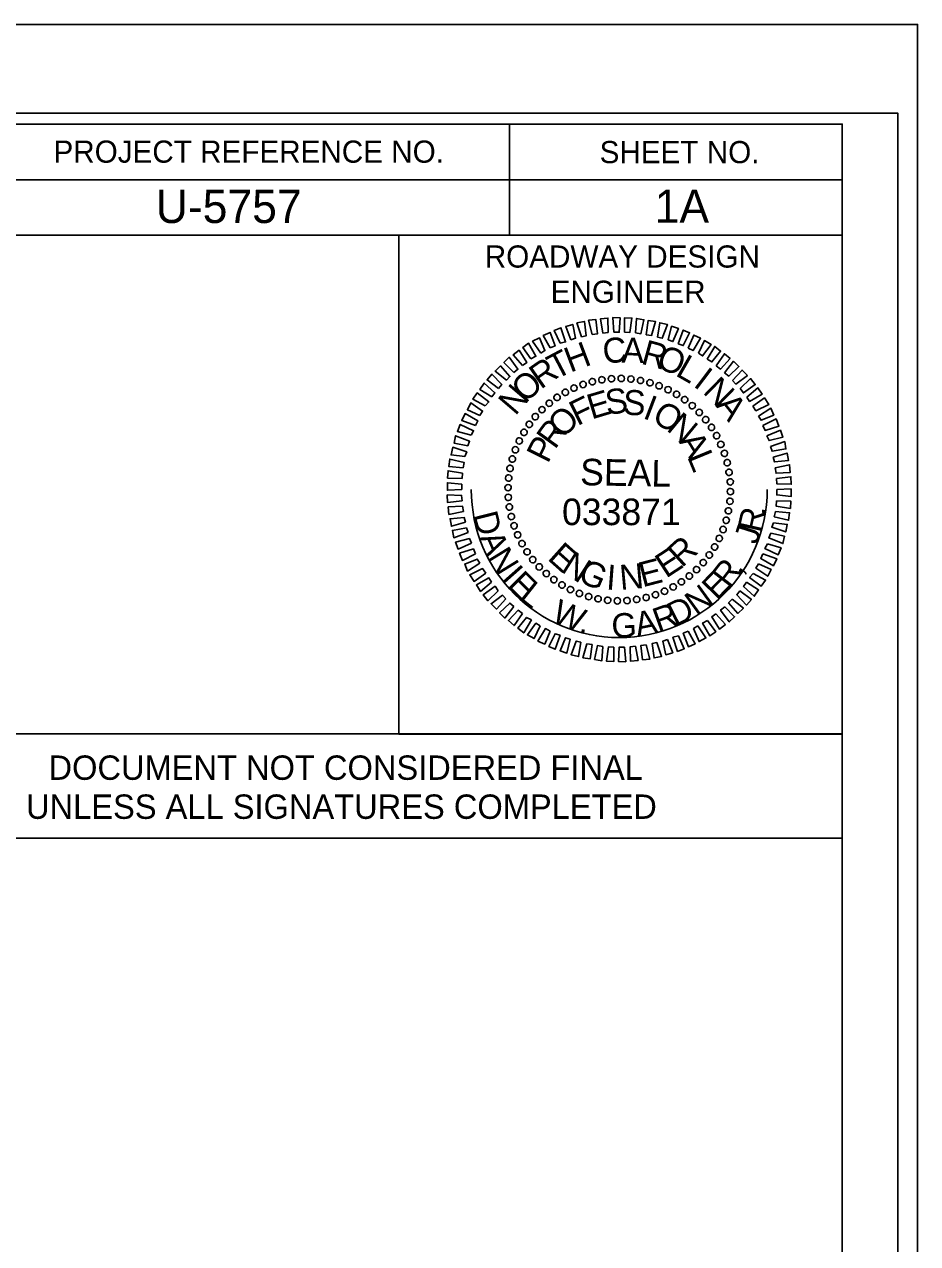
# Model space of a CAD drawing. Extents: x 1537922 to 1539606, y 409903 to 410998.
# Drawn here: x 1539404.5 to 1539605.9, y 410723.4 to 410998.4 of the extents above; entities that cross this region are included whole.
import ezdxf

# ---------------------------------------------------------------- set-up
doc = ezdxf.new("R2010")
doc.units = 0
for name, color, linetype in [('Scratch_Level_0', 7, 'Continuous'), ('Sheet Cutting Line CELL', 7, 'Continuous'), ('Sheet Data Field CELL', 7, 'Continuous'), ('Sheet Plan CELL', 7, 'Continuous'), ('Sheet Plot Border Inside CELL', 7, 'Continuous'), ('Sheet Plot Border Outside CELL', 7, 'Continuous'), ('Sheet Professional Seal CELL', 7, 'Continuous'), ('Sheet Profile Grid Minor CELL', 7, 'Continuous'), ('Sheet Sticker Exception Certification CELL', 7, 'Continuous')]:
    doc.layers.add(name, color=color, linetype=linetype)

msp = doc.modelspace()

# ---------------------------------------------------------------- linework, layer by layer
at = {"layer": 'Scratch_Level_0'}
msp.add_arc((1539538.59, 410893.42), 33.36, 180, 360, dxfattribs=at)
at = {"layer": 'Sheet Cutting Line CELL'}
msp.add_line((1539605.87, 410998.35), (1537922.37, 410998.35), dxfattribs=at)
at = {"layer": 'Sheet Plan CELL'}
for p, q in [((1539513.87, 410975.8), (1539513.87, 410950.8)), ((1539388.82, 410963.3), (1539588.87, 410963.3)), ((1539388.82, 410950.8), (1539588.87, 410950.8)), ((1539388.82, 410950.8), (1539588.87, 410950.8)), ((1539488.87, 410950.8), (1539488.87, 410838.35))]:
    msp.add_line(p, q, dxfattribs=at)
for points in [[(1539588.87, 410975.85), (1538088.87, 410975.85), (1538088.87, 409925.85), (1539588.87, 409925.85)], [(1539388.82, 410975.85), (1539588.87, 410975.85), (1539588.87, 410950.8), (1539388.82, 410950.8)], [(1539488.87, 410950.8), (1539588.87, 410950.8), (1539588.87, 410838.3), (1539488.87, 410838.3)]]:
    msp.add_lwpolyline(points, close=True, dxfattribs=at)
at = {"layer": 'Sheet Plot Border Inside CELL'}
msp.add_lwpolyline([(1537935.37, 409923.35), (1539601.37, 409923.35), (1539601.37, 410978.35), (1537935.37, 410978.35)], close=True, dxfattribs=at)
at = {"layer": 'Sheet Plot Border Outside CELL'}
msp.add_lwpolyline([(1537922.37, 409903.35), (1539605.87, 409903.35), (1539605.87, 410998.35), (1537922.37, 410998.35)], close=True, dxfattribs=at)
at = {"layer": 'Sheet Professional Seal CELL'}
for p, q in [((1539534.69, 410918.17), (1539534.69, 410918.17)), ((1539536.84, 410918.47), (1539536.84, 410918.47)), ((1539539.04, 410918.52), (1539539.04, 410918.52)), ((1539541.24, 410918.37), (1539541.24, 410918.37)), ((1539543.39, 410918.02), (1539543.39, 410918.02)), ((1539526.44, 410915.37), (1539526.44, 410915.37)), ((1539528.39, 410916.37), (1539528.39, 410916.37)), ((1539530.39, 410917.17), (1539530.39, 410917.17)), ((1539532.49, 410917.77), (1539532.49, 410917.77)), ((1539545.49, 410917.57), (1539545.49, 410917.57)), ((1539547.59, 410916.87), (1539547.59, 410916.87)), ((1539549.59, 410915.97), (1539549.59, 410915.97)), ((1539522.79, 410912.97), (1539522.79, 410912.97)), ((1539524.54, 410914.22), (1539524.54, 410914.22)), ((1539551.54, 410914.97), (1539551.54, 410914.97)), ((1539553.34, 410913.72), (1539553.34, 410913.72)), ((1539519.64, 410909.92), (1539519.64, 410909.92)), ((1539521.14, 410911.47), (1539521.14, 410911.47)), ((1539555.09, 410912.37), (1539555.09, 410912.37)), ((1539556.64, 410910.87), (1539556.64, 410910.87)), ((1539518.29, 410908.17), (1539518.29, 410908.17)), ((1539558.14, 410909.22), (1539558.14, 410909.22)), ((1539559.39, 410907.47), (1539559.39, 410907.47)), ((1539516.04, 410904.42), (1539516.04, 410904.42)), ((1539517.04, 410906.37), (1539517.04, 410906.37)), ((1539560.54, 410905.57), (1539560.54, 410905.57)), ((1539515.14, 410902.42), (1539515.14, 410902.42)), ((1539561.54, 410903.62), (1539561.54, 410903.62)), ((1539562.34, 410901.62), (1539562.34, 410901.62)), ((1539514.44, 410900.32), (1539514.44, 410900.32)), ((1539562.94, 410899.52), (1539562.94, 410899.52)), ((1539513.64, 410896.07), (1539513.64, 410896.07)), ((1539513.99, 410898.22), (1539513.99, 410898.22)), ((1539563.34, 410897.32), (1539563.34, 410897.32)), ((1539513.49, 410893.87), (1539513.49, 410893.87)), ((1539538.59, 410893.42), (1539538.59, 410893.42)), ((1539563.64, 410895.17), (1539563.64, 410895.17)), ((1539513.54, 410891.67), (1539513.54, 410891.67)), ((1539563.54, 410890.77), (1539563.54, 410890.77)), ((1539563.69, 410892.97), (1539563.69, 410892.97)), ((1539513.84, 410889.52), (1539513.84, 410889.52)), ((1539563.19, 410888.62), (1539563.19, 410888.62)), ((1539514.24, 410887.32), (1539514.24, 410887.32)), ((1539514.84, 410885.22), (1539514.84, 410885.22)), ((1539562.74, 410886.52), (1539562.74, 410886.52)), ((1539515.64, 410883.22), (1539515.64, 410883.22)), ((1539561.14, 410882.42), (1539561.14, 410882.42)), ((1539562.04, 410884.42), (1539562.04, 410884.42)), ((1539516.64, 410881.27), (1539516.64, 410881.27)), ((1539560.14, 410880.47), (1539560.14, 410880.47)), ((1539517.79, 410879.37), (1539517.79, 410879.37)), ((1539519.04, 410877.62), (1539519.04, 410877.62)), ((1539557.54, 410876.92), (1539557.54, 410876.92)), ((1539558.89, 410878.67), (1539558.89, 410878.67)), ((1539520.54, 410875.97), (1539520.54, 410875.97)), ((1539522.09, 410874.47), (1539522.09, 410874.47)), ((1539556.04, 410875.37), (1539556.04, 410875.37)), ((1539523.84, 410873.12), (1539523.84, 410873.12)), ((1539525.64, 410871.87), (1539525.64, 410871.87)), ((1539550.74, 410871.47), (1539550.74, 410871.47)), ((1539552.64, 410872.62), (1539552.64, 410872.62)), ((1539554.39, 410873.87), (1539554.39, 410873.87)), ((1539527.59, 410870.87), (1539527.59, 410870.87)), ((1539529.59, 410869.97), (1539529.59, 410869.97)), ((1539531.69, 410869.27), (1539531.69, 410869.27)), ((1539533.79, 410868.82), (1539533.79, 410868.82)), ((1539542.49, 410868.67), (1539542.49, 410868.67)), ((1539544.69, 410869.07), (1539544.69, 410869.07)), ((1539546.79, 410869.67), (1539546.79, 410869.67)), ((1539548.79, 410870.47), (1539548.79, 410870.47)), ((1539535.94, 410868.47), (1539535.94, 410868.47)), ((1539538.14, 410868.32), (1539538.14, 410868.32)), ((1539540.34, 410868.37), (1539540.34, 410868.37))]:
    msp.add_line(p, q, dxfattribs=at)
for points in [[(1539532.49, 410928.42), (1539531.69, 410931.62), (1539533.34, 410931.77), (1539533.69, 410928.57)], [(1539534.89, 410928.72), (1539534.34, 410931.92), (1539536.04, 410932.12), (1539536.09, 410928.87)], [(1539537.39, 410928.97), (1539537.14, 410932.22), (1539538.79, 410932.17), (1539538.59, 410928.92)], [(1539539.79, 410928.92), (1539539.79, 410932.17), (1539541.44, 410932.12), (1539540.99, 410928.87)], [(1539542.29, 410928.77), (1539542.49, 410932.02), (1539544.14, 410931.72), (1539543.49, 410928.57)], [(1539525.24, 410926.42), (1539523.94, 410929.32), (1539525.44, 410929.92), (1539526.49, 410926.72)], [(1539527.69, 410927.22), (1539526.54, 410930.22), (1539528.09, 410930.67), (1539528.74, 410927.57)], [(1539530.09, 410927.87), (1539529.04, 410931.02), (1539530.74, 410931.37), (1539531.14, 410928.12)], [(1539544.69, 410928.37), (1539545.14, 410931.57), (1539546.79, 410931.32), (1539545.89, 410928.22)], [(1539547.24, 410927.82), (1539547.74, 410931.07), (1539549.44, 410930.67), (1539548.29, 410927.57)], [(1539549.64, 410927.17), (1539550.39, 410930.27), (1539551.94, 410929.77), (1539550.69, 410926.82)], [(1539551.89, 410926.27), (1539553.04, 410929.42), (1539554.44, 410928.82), (1539553.04, 410925.92)], [(1539518.69, 410922.92), (1539516.84, 410925.47), (1539518.14, 410926.42), (1539519.79, 410923.52)], [(1539520.89, 410924.17), (1539519.04, 410926.87), (1539520.59, 410927.67), (1539521.84, 410924.77)], [(1539523.04, 410925.37), (1539521.44, 410928.17), (1539522.99, 410928.87), (1539524.14, 410925.82)], [(1539554.14, 410925.32), (1539555.39, 410928.27), (1539556.94, 410927.57), (1539555.24, 410924.77)], [(1539556.44, 410924.17), (1539557.79, 410927.02), (1539559.29, 410926.17), (1539557.39, 410923.57)], [(1539516.79, 410921.42), (1539514.64, 410923.82), (1539515.99, 410924.87), (1539517.74, 410922.07)], [(1539558.39, 410922.82), (1539560.14, 410925.72), (1539561.44, 410924.67), (1539559.49, 410922.22)], [(1539560.44, 410921.32), (1539562.29, 410924.07), (1539563.59, 410922.97), (1539561.39, 410920.62)], [(1539513.14, 410918.12), (1539510.59, 410920.17), (1539511.84, 410921.32), (1539513.94, 410918.92)], [(1539514.79, 410919.87), (1539512.59, 410922.07), (1539513.79, 410923.27), (1539515.74, 410920.57)], [(1539562.34, 410919.77), (1539564.39, 410922.37), (1539565.59, 410921.17), (1539563.29, 410919.02)], [(1539511.39, 410916.22), (1539508.79, 410918.17), (1539509.89, 410919.47), (1539512.09, 410917.12)], [(1539564.14, 410918.02), (1539566.29, 410920.37), (1539567.49, 410919.17), (1539564.89, 410917.22)], [(1539565.89, 410916.22), (1539568.19, 410918.47), (1539569.24, 410917.12), (1539566.59, 410915.22)], [(1539509.89, 410914.32), (1539507.19, 410916.02), (1539508.14, 410917.47), (1539510.54, 410915.27)], [(1539567.39, 410914.27), (1539569.84, 410916.37), (1539570.79, 410914.92), (1539567.99, 410913.32)], [(1539507.19, 410910.17), (1539504.34, 410911.42), (1539505.09, 410912.97), (1539507.79, 410911.12)], [(1539508.39, 410912.32), (1539505.59, 410913.82), (1539506.59, 410915.22), (1539509.19, 410913.22)], [(1539568.69, 410912.22), (1539571.34, 410914.12), (1539572.29, 410912.62), (1539569.39, 410911.22)], [(1539506.19, 410907.87), (1539503.09, 410909.02), (1539503.84, 410910.57), (1539506.69, 410908.97)], [(1539569.99, 410910.02), (1539572.79, 410911.77), (1539573.44, 410910.22), (1539570.59, 410909.07)], [(1539505.19, 410905.67), (1539502.09, 410906.57), (1539502.74, 410908.12), (1539505.74, 410906.72)], [(1539570.99, 410907.87), (1539573.94, 410909.37), (1539574.59, 410907.77), (1539571.49, 410906.77)], [(1539504.44, 410903.27), (1539501.34, 410903.92), (1539501.69, 410905.57), (1539504.84, 410904.32)], [(1539571.89, 410905.52), (1539574.94, 410906.82), (1539575.49, 410905.27), (1539572.39, 410904.47)], [(1539572.69, 410903.12), (1539575.89, 410904.27), (1539576.19, 410902.62), (1539573.04, 410902.07)], [(1539503.79, 410900.87), (1539500.69, 410901.27), (1539501.04, 410902.97), (1539504.19, 410901.92)], [(1539573.29, 410900.72), (1539576.44, 410901.67), (1539576.74, 410899.97), (1539573.59, 410899.67)], [(1539503.39, 410898.32), (1539500.19, 410898.62), (1539500.39, 410900.32), (1539503.64, 410899.52)], [(1539573.74, 410898.32), (1539576.99, 410899.02), (1539577.14, 410897.32), (1539573.94, 410897.12)], [(1539503.14, 410895.92), (1539499.89, 410896.02), (1539499.99, 410897.67), (1539503.24, 410897.12)], [(1539574.04, 410895.92), (1539577.29, 410896.32), (1539577.39, 410894.62), (1539574.14, 410894.72)], [(1539503.09, 410893.42), (1539499.84, 410893.27), (1539499.84, 410894.97), (1539503.09, 410894.62)], [(1539574.09, 410893.42), (1539577.34, 410893.57), (1539577.34, 410891.87), (1539574.09, 410892.22)], [(1539503.14, 410890.92), (1539499.89, 410890.52), (1539499.79, 410892.22), (1539503.04, 410892.12)], [(1539574.04, 410890.92), (1539577.29, 410890.82), (1539577.19, 410889.17), (1539573.94, 410889.72)], [(1539503.44, 410888.52), (1539500.19, 410887.82), (1539500.04, 410889.52), (1539503.24, 410889.72)], [(1539573.79, 410888.52), (1539576.99, 410888.22), (1539576.79, 410886.52), (1539573.54, 410887.32)], [(1539503.89, 410886.12), (1539500.74, 410885.17), (1539500.44, 410886.87), (1539503.59, 410887.17)], [(1539573.39, 410885.97), (1539576.49, 410885.57), (1539576.14, 410883.87), (1539572.99, 410884.92)], [(1539504.49, 410883.72), (1539501.29, 410882.57), (1539500.99, 410884.22), (1539504.14, 410884.77)], [(1539505.29, 410881.32), (1539502.24, 410880.02), (1539501.69, 410881.57), (1539504.79, 410882.37)], [(1539572.74, 410883.57), (1539575.84, 410882.92), (1539575.49, 410881.27), (1539572.34, 410882.52)], [(1539506.19, 410878.97), (1539503.24, 410877.47), (1539502.59, 410879.07), (1539505.69, 410880.07)], [(1539571.99, 410881.17), (1539575.09, 410880.27), (1539574.44, 410878.72), (1539571.44, 410880.12)], [(1539507.19, 410876.82), (1539504.39, 410875.07), (1539503.74, 410876.62), (1539506.59, 410877.77)], [(1539570.99, 410878.97), (1539574.09, 410877.82), (1539573.34, 410876.27), (1539570.49, 410877.87)], [(1539508.49, 410874.62), (1539505.84, 410872.72), (1539504.89, 410874.22), (1539507.79, 410875.62)], [(1539568.79, 410874.52), (1539571.59, 410873.02), (1539570.59, 410871.62), (1539567.99, 410873.62)], [(1539569.99, 410876.67), (1539572.84, 410875.42), (1539572.09, 410873.87), (1539569.39, 410875.72)], [(1539509.79, 410872.57), (1539507.34, 410870.47), (1539506.39, 410871.92), (1539509.19, 410873.52)], [(1539511.29, 410870.62), (1539508.99, 410868.37), (1539507.94, 410869.72), (1539510.59, 410871.62)], [(1539567.29, 410872.52), (1539569.99, 410870.82), (1539569.04, 410869.37), (1539566.64, 410871.57)], [(1539513.04, 410868.82), (1539510.89, 410866.47), (1539509.69, 410867.67), (1539512.29, 410869.62)], [(1539564.04, 410868.72), (1539566.59, 410866.67), (1539565.34, 410865.52), (1539563.24, 410867.92)], [(1539565.79, 410870.62), (1539568.39, 410868.67), (1539567.29, 410867.37), (1539565.09, 410869.72)], [(1539514.84, 410867.07), (1539512.79, 410864.47), (1539511.59, 410865.67), (1539513.89, 410867.82)], [(1539516.74, 410865.52), (1539514.89, 410862.77), (1539513.59, 410863.87), (1539515.79, 410866.22)], [(1539562.39, 410866.97), (1539564.59, 410864.77), (1539563.39, 410863.57), (1539561.44, 410866.27)], [(1539518.79, 410864.02), (1539517.04, 410861.12), (1539515.74, 410862.17), (1539517.69, 410864.62)], [(1539520.74, 410862.67), (1539519.39, 410859.82), (1539517.89, 410860.67), (1539519.79, 410863.27)], [(1539558.49, 410863.92), (1539560.34, 410861.37), (1539559.04, 410860.42), (1539557.39, 410863.32)], [(1539560.39, 410865.42), (1539562.54, 410863.02), (1539561.19, 410861.97), (1539559.44, 410864.77)], [(1539523.04, 410861.52), (1539521.79, 410858.57), (1539520.24, 410859.27), (1539521.94, 410862.07)], [(1539525.29, 410860.57), (1539524.14, 410857.42), (1539522.74, 410858.02), (1539524.14, 410860.92)], [(1539551.94, 410860.42), (1539553.24, 410857.52), (1539551.74, 410856.92), (1539550.69, 410860.12)], [(1539554.14, 410861.47), (1539555.74, 410858.67), (1539554.19, 410857.97), (1539553.04, 410861.02)], [(1539556.29, 410862.67), (1539558.14, 410859.97), (1539556.59, 410859.17), (1539555.34, 410862.07)], [(1539527.54, 410859.67), (1539526.79, 410856.57), (1539525.24, 410857.07), (1539526.49, 410860.02)], [(1539529.94, 410859.02), (1539529.44, 410855.77), (1539527.74, 410856.17), (1539528.89, 410859.27)], [(1539532.49, 410858.47), (1539532.04, 410855.27), (1539530.39, 410855.52), (1539531.29, 410858.62)], [(1539534.89, 410858.07), (1539534.69, 410854.82), (1539533.04, 410855.12), (1539533.69, 410858.27)], [(1539537.39, 410857.92), (1539537.39, 410854.67), (1539535.74, 410854.72), (1539536.19, 410857.97)], [(1539539.79, 410857.87), (1539540.04, 410854.62), (1539538.39, 410854.67), (1539538.59, 410857.92)], [(1539542.29, 410858.12), (1539542.84, 410854.92), (1539541.14, 410854.72), (1539541.09, 410857.97)], [(1539544.69, 410858.42), (1539545.49, 410855.22), (1539543.84, 410855.07), (1539543.49, 410858.27)], [(1539547.09, 410858.97), (1539548.14, 410855.82), (1539546.44, 410855.47), (1539546.04, 410858.72)], [(1539549.49, 410859.62), (1539550.64, 410856.62), (1539549.09, 410856.17), (1539548.44, 410859.27)]]:
    msp.add_lwpolyline(points, close=True, dxfattribs=at)
for centre, major_axis in [((1539532.53, 410917.76), (-0.174, 0.699)), ((1539534.67, 410918.19), (-0.113, 0.711)), ((1539536.84, 410918.44), (-0.05, 0.718)), ((1539539.03, 410918.5), (0.013, 0.72)), ((1539541.21, 410918.36), (0.075, 0.716)), ((1539543.38, 410918.04), (0.137, 0.707)), ((1539545.51, 410917.53), (0.198, 0.692)), ((1539526.43, 410915.36), (-0.349, 0.63)), ((1539528.39, 410916.33), (-0.293, 0.658)), ((1539530.43, 410917.13), (-0.234, 0.681)), ((1539547.58, 410916.84), (0.258, 0.672)), ((1539549.59, 410915.96), (0.316, 0.647)), ((1539551.51, 410914.92), (0.371, 0.617)), ((1539522.81, 410912.91), (-0.453, 0.56)), ((1539524.57, 410914.21), (-0.403, 0.597)), ((1539553.33, 410913.71), (0.423, 0.582)), ((1539555.05, 410912.35), (0.472, 0.543)), ((1539519.66, 410909.88), (-0.543, 0.472)), ((1539521.17, 410911.46), (-0.5, 0.518)), ((1539556.63, 410910.84), (0.518, 0.5)), ((1539558.08, 410909.2), (0.56, 0.453)), ((1539517.1, 410906.34), (-0.617, 0.371)), ((1539518.3, 410908.16), (-0.582, 0.423)), ((1539559.39, 410907.45), (0.597, 0.403)), ((1539516.05, 410904.42), (-0.647, 0.316)), ((1539560.53, 410905.58), (0.63, 0.349)), ((1539561.5, 410903.62), (0.658, 0.293)), ((1539515.18, 410902.41), (-0.672, 0.258)), ((1539562.31, 410901.59), (0.681, 0.234)), ((1539513.97, 410898.21), (-0.707, 0.137)), ((1539514.48, 410900.33), (-0.692, 0.198)), ((1539562.93, 410899.49), (0.699, 0.174)), ((1539513.65, 410896.04), (-0.716, 0.075)), ((1539563.36, 410897.34), (0.711, 0.113)), ((1539513.52, 410893.86), (-0.72, 0.013)), ((1539563.61, 410895.17), (0.718, 0.05)), ((1539563.67, 410892.98), (0.72, -0.013)), ((1539513.57, 410891.67), (-0.718, -0.05)), ((1539563.54, 410890.8), (0.716, -0.075)), ((1539513.82, 410889.5), (-0.711, -0.113)), ((1539514.26, 410887.35), (-0.699, -0.174)), ((1539563.21, 410888.64), (0.707, -0.137)), ((1539514.88, 410885.26), (-0.681, -0.234)), ((1539562.01, 410884.43), (0.672, -0.258)), ((1539562.7, 410886.51), (0.692, -0.198)), ((1539515.68, 410883.22), (-0.658, -0.293)), ((1539561.13, 410882.43), (0.647, -0.316)), ((1539516.66, 410881.26), (-0.63, -0.349)), ((1539517.8, 410879.4), (-0.597, -0.403)), ((1539558.88, 410878.68), (0.582, -0.423)), ((1539560.09, 410880.5), (0.617, -0.371)), ((1539519.1, 410877.64), (-0.56, -0.453)), ((1539520.55, 410876), (-0.518, -0.5)), ((1539557.52, 410876.97), (0.543, -0.472)), ((1539522.14, 410874.49), (-0.472, -0.543)), ((1539554.38, 410873.93), (0.453, -0.56)), ((1539556.02, 410875.38), (0.5, -0.518)), ((1539523.85, 410873.13), (-0.423, -0.582)), ((1539525.68, 410871.92), (-0.371, -0.617)), ((1539527.6, 410870.88), (-0.316, -0.647)), ((1539548.79, 410870.51), (0.293, -0.658)), ((1539550.75, 410871.49), (0.349, -0.63)), ((1539552.62, 410872.63), (0.403, -0.597)), ((1539529.61, 410870.01), (-0.258, -0.672)), ((1539531.68, 410869.31), (-0.198, -0.692)), ((1539533.81, 410868.8), (-0.137, -0.707)), ((1539535.97, 410868.48), (-0.075, -0.716)), ((1539538.16, 410868.34), (-0.013, -0.72)), ((1539540.34, 410868.4), (0.05, -0.718)), ((1539542.52, 410868.65), (0.113, -0.711)), ((1539544.66, 410869.09), (0.174, -0.699)), ((1539546.76, 410869.71), (0.234, -0.681))]:
    msp.add_ellipse(centre, major_axis=major_axis, ratio=0.999708, dxfattribs=at)
at = {"layer": 'Sheet Sticker Exception Certification CELL'}
for p, q in [((1539388.83, 410838.31), (1539588.87, 410838.31)), ((1539588.87, 410838.3), (1539588.87, 410814.8)), ((1539588.87, 410814.81), (1539388.83, 410814.81))]:
    msp.add_line(p, q, dxfattribs=at)

# ---------------------------------------------------------------- texts
at = {"layer": 'Sheet Data Field CELL'}
for s, p in [('U-5757', (1539434.08, 410953.55)), ('1A', (1539546.58, 410953.6))]:
    msp.add_text(s, height=7.5, dxfattribs=at).set_placement(p)
at = {"layer": 'Sheet Plan CELL'}
for s, height, p in [('PROJECT REFERENCE NO.', 5.0001, (1539411.02, 410967.15)), ('SHEET NO.', 5, (1539534.17, 410967.05)), ('ROADWAY DESIGN', 5.0001, (1539508.27, 410943.5)), ('ENGINEER', 5, (1539523.12, 410935.55))]:
    msp.add_text(s, height=height, dxfattribs=at).set_placement(p)
at = {"layer": 'Sheet Professional Seal CELL'}
for s, height, rotation, p in [('H', 5.64, 20.6195, (1539527.54, 410919.77)), ('C', 5.64, 6.2199, (1539535.14, 410921.77)), ('A', 5.64, 359.0203, (1539539.09, 410922.07)), ('R', 5.64, 344.6211, (1539543.29, 410921.87)), ('T', 5.64, 27.8198, (1539524.29, 410918.12)), ('O', 5.64, 337.4212, (1539546.64, 410921.12)), ('L', 5.64, 330.2209, (1539551.04, 410919.27)), ('R', 5.64, 35.0205, (1539520.89, 410915.92)), ('I', 5.64, 323.0201, (1539555.09, 410916.87)), ('O', 5.64, 42.2217, (1539517.44, 410912.82)), ('N', 5.64, 315.8189, (1539557.24, 410915.32)), ('N', 5.64, 49.4235, (1539515.14, 410909.92)), ('E', 5.64, 16.6111, (1539532.34, 410909.22)), ('S', 5.64, 7.2556, (1539535.79, 410910.27)), ('S', 5.64, 357.9004, (1539539.39, 410910.32)), ('F', 5.64, 25.967, (1539529.14, 410907.72)), ('I', 5.64, 339.1896, (1539543.69, 410909.62)), ('O', 5.64, 329.8335, (1539545.69, 410908.92)), ('A', 5.64, 308.6172, (1539560.19, 410912.37)), ('O', 5.64, 44.6812, (1539525.84, 410904.77)), ('N', 5.64, 320.4766, (1539549.04, 410906.92)), ('R', 5.64, 54.0397, (1539524.09, 410902.32)), ('P', 5.64, 63.3989, (1539522.49, 410899.12)), ('A', 5.64, 301.7603, (1539551.89, 410904.32)), ('L', 5.64, 292.4008, (1539553.84, 410900.87)), ('SEAL', 5.998, 359, (1539529.74, 410894.42)), ('R', 5.64, 42.4814, (1539552.69, 410875.67)), ('E', 5.64, 318.2769, (1539522.19, 410877.77)), ('N', 5.64, 327.634, (1539525.19, 410875.07)), ('E', 5.64, 33.1241, (1539549.14, 410873.32)), ('G', 5.64, 336.9902, (1539528.99, 410872.82)), ('N', 5.64, 5.0564, (1539538.89, 410870.77)), ('E', 5.64, 14.4118, (1539543.84, 410871.37)), ('I', 5.64, 355.7012, (1539535.54, 410870.92))]:
    msp.add_text(s, height=height, rotation=rotation, dxfattribs=at).set_placement(p)
at = {"layer": 'Sheet Profile Grid Minor CELL'}
msp.add_text('033871', height=5.998, dxfattribs=at).set_placement((1539525.69, 410885.41))
for s, rotation, p in [('D', 284.2682, (1539505.6, 410887.78)), ('R', 77.3541, (1539570.56, 410883.52)), ('.', 84.2805, (1539571.53, 410887.45)), ('J', 72.4855, (1539569.61, 410880.84)), ('A', 293.4128, (1539506.92, 410882.61)), ('N', 301.5986, (1539508.78, 410878.21)), ('R', 52.3788, (1539563.39, 410870.95)), ('I', 311.5304, (1539511.85, 410873.29)), ('E', 315.0508, (1539513.14, 410871.69)), ('E', 45.7958, (1539560.65, 410868.25)), (',', 59.3052, (1539565.92, 410874.1)), ('L', 321.6338, (1539515.8, 410868.91)), ('N', 35.8641, (1539555.98, 410864.82)), ('W', 336.8891, (1539523.05, 410863.78)), ('D', 26.7195, (1539551.22, 410862.42)), ('A', 11.6072, (1539542.7, 410860.2)), ('R', 19.793, (1539547.39, 410861.13)), ('G', 1.6755, (1539536.91, 410859.99)), ('.', 348.4952, (1539529.33, 410861.26))]:
    msp.add_text(s, height=5.5, rotation=rotation, dxfattribs=at).set_placement(p)
at = {"layer": 'Sheet Sticker Exception Certification CELL'}
for s, p in [('DOCUMENT NOT CONSIDERED FINAL', (1539409.9, 410827.97)), ('UNLESS ALL SIGNATURES COMPLETED', (1539404.83, 410819.17))]:
    msp.add_text(s, height=5.5, dxfattribs=at).set_placement(p)

doc.saveas('drawing.dxf')
